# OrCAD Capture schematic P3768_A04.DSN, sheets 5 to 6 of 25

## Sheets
5 0020_M.2 KEY-E _WIFI_BT_: size Custom
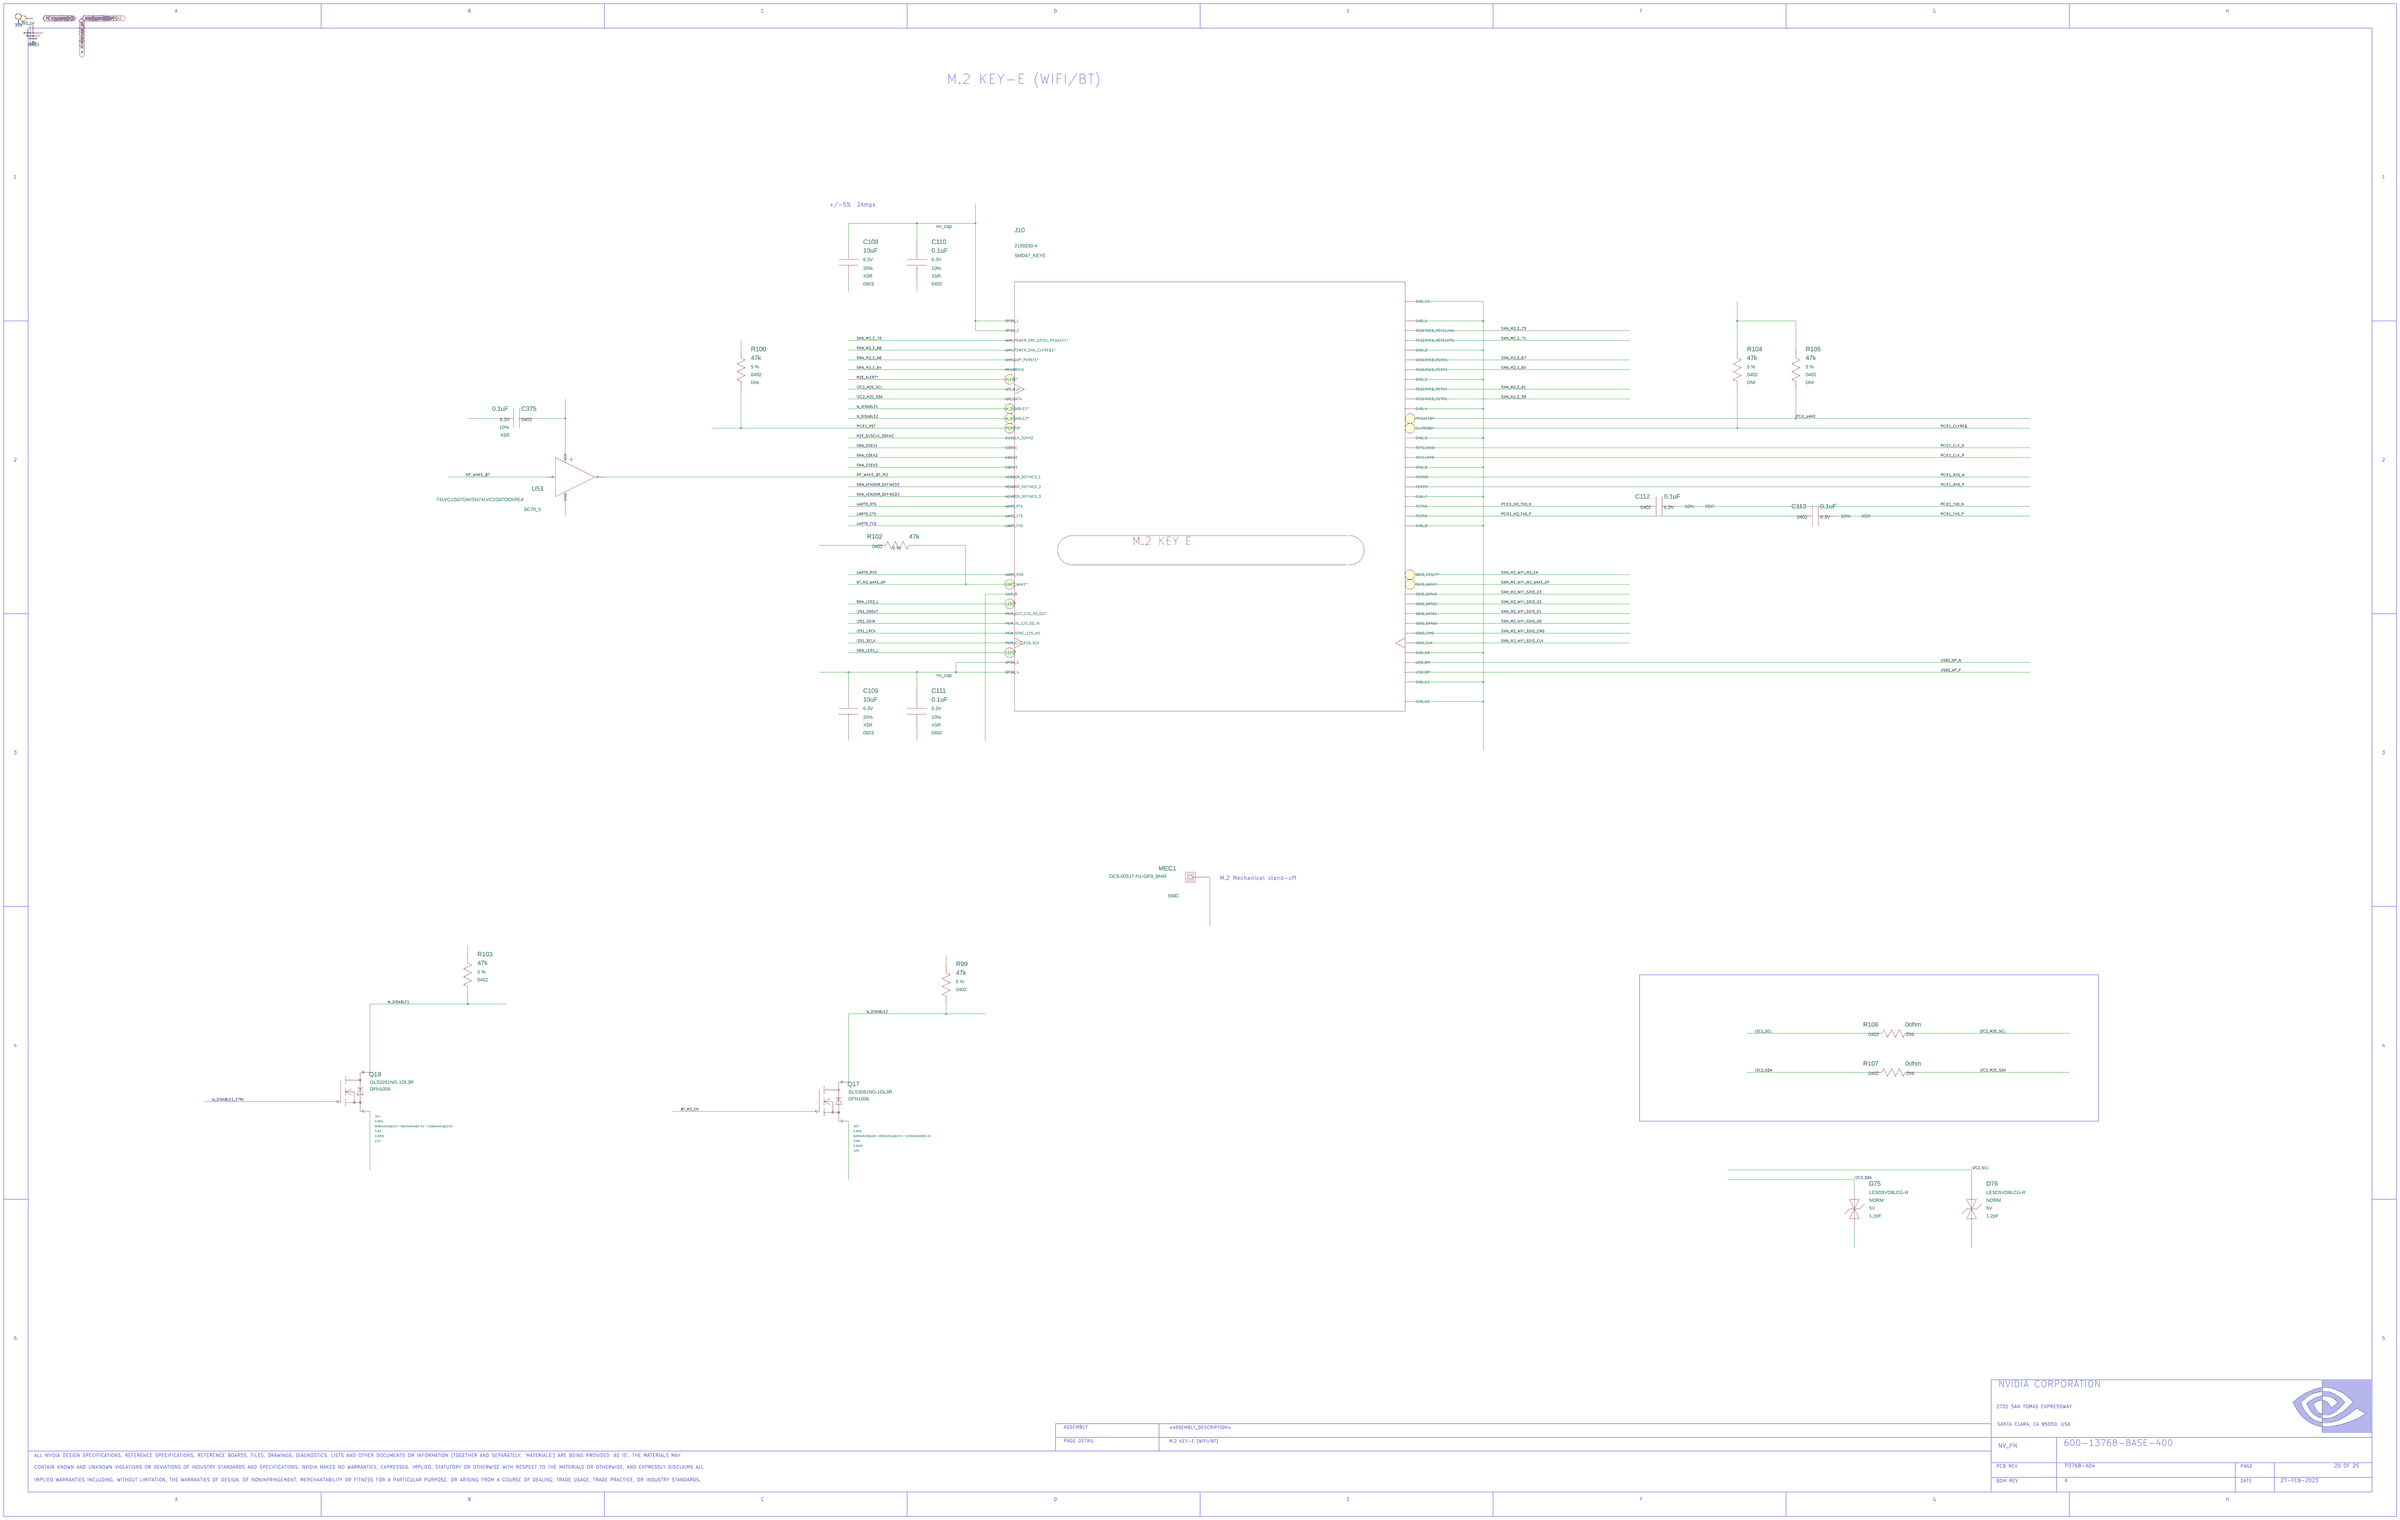
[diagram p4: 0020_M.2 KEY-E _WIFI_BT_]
6 0019_ETHERNET: size Custom
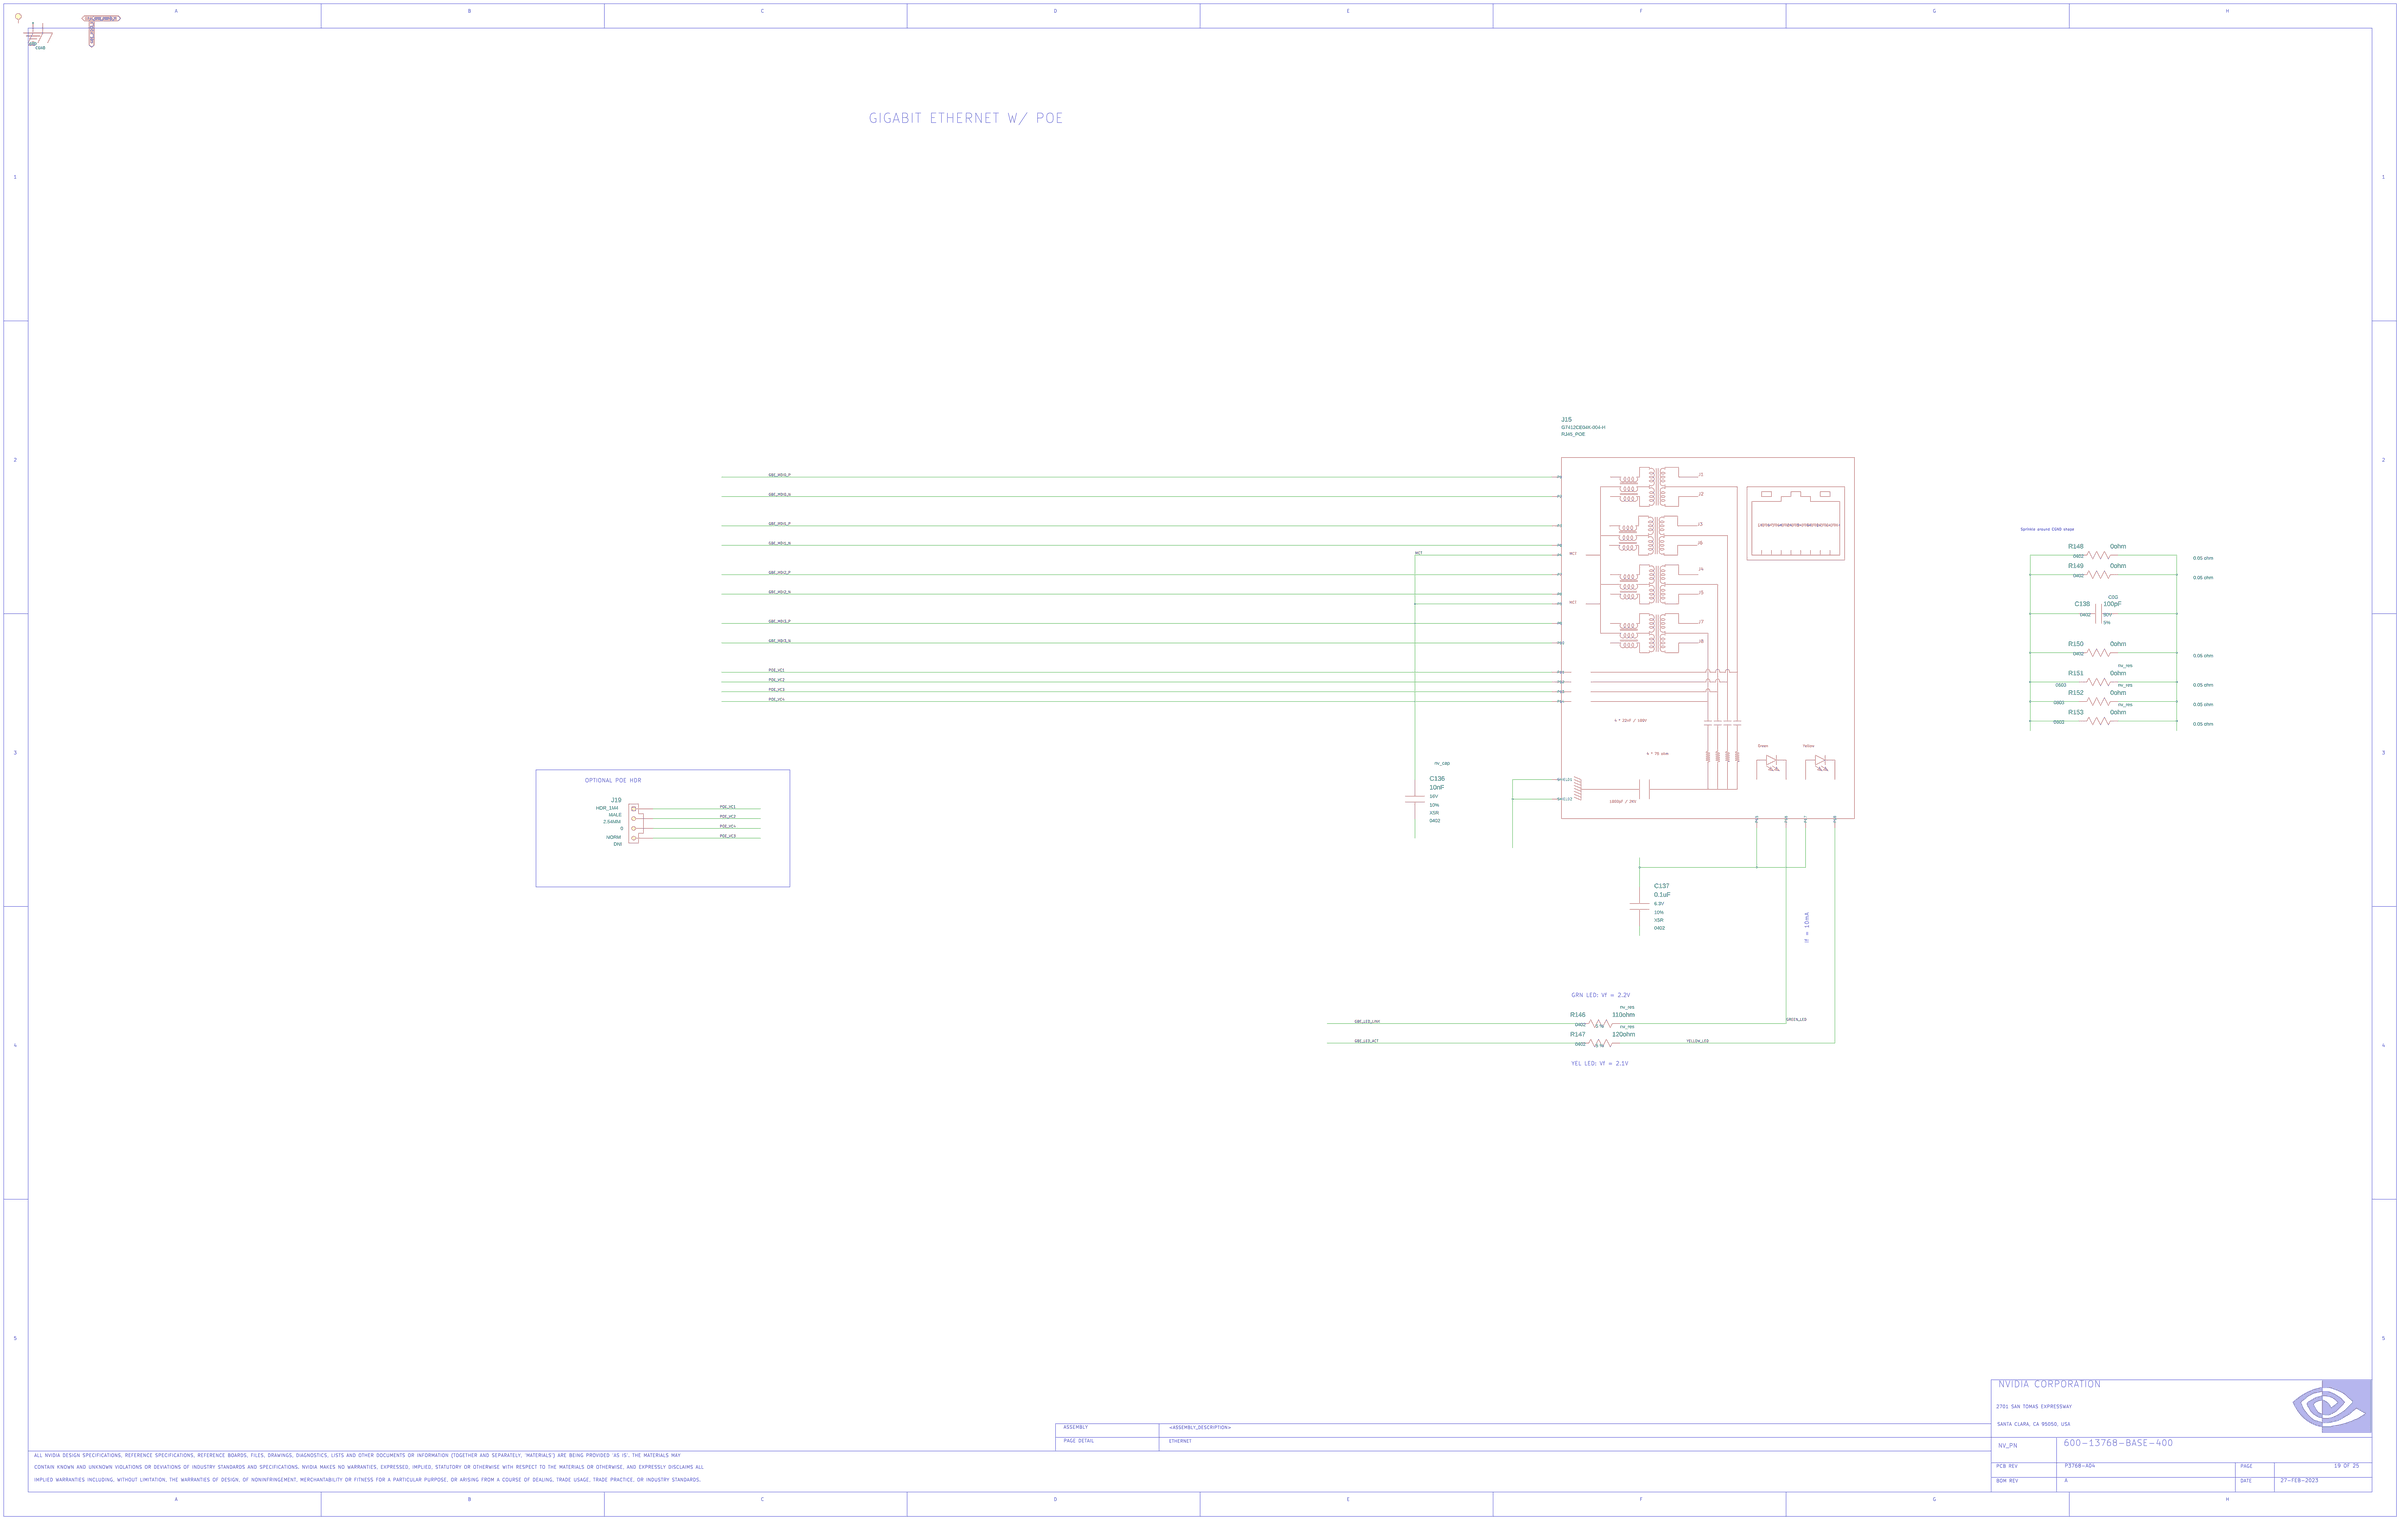
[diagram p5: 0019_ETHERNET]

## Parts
sheet 0019_ETHERNET
C136  10nF  [0402]
C137  0.1uF  [0402]
C138  100pF  [0402]
J15  CON_RJ45  [CON_RJ45_018_TH_RA_F_2LED]
J19  HDR_1X4  [CON_HDR_001X004_TH_ST_M_P025]
R146  110ohm  [0402]
R147  120ohm  [0402]
R148  0ohm  [0402]
R149  0ohm  [0402]
R150  0ohm  [0402]
R151  0ohm  [0603]
R152  0ohm  [0603]
R153  0ohm  [0603]
sheet 0020_M.2 KEY-E _WIFI_BT_
C108  10uF  [0603]
C109  10uF  [0603]
C110  0.1uF  [0402]
C111  0.1uF  [0402]
C112  0.1uF  [0402]
C113  0.1uF  [0402]
C375  0.1uF  [0402]
D75  D_ESD  [DIODE_SMD_010X006_B]
D76  D_ESD  [DIODE_SMD_010X006_B]
J10  CON_M2_PCI_EXP  [CON_MINIPEX_067_SMT_RA_M2_KEYE]
MEC1  MECH_SPECIAL  [MEC_STANDOFF_PTH_620C380P_M3_BNM]
Q17  Q_FET_N_ENH  [DFET_003_SMD_010X006_B]
Q18  Q_FET_N_ENH  [DFET_003_SMD_010X006_B]
R99  47k  [0402]
R100  47k  [0402]
R102  47k  [0402]
R103  47k  [0402]
R104  47k  [0402]
R105  47k  [0402]
R106  0ohm  [0402]
R107  0ohm  [0402]
U53  U_BUF_OD  [SC70_5]

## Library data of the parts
C136 = C#1: ASSEMBLY: ETHERNET; CDS_LIB: discrete; CDS_PART_NAME: C_0402-10NF,X5R,10%,16V,039-0024-000; CDS_PHYS_PART_NAME: C_0402-10NF,X5R,10%,16V,039-0024-000-039-0024-000,10NF; CDS_SEC: 1; CHIPS_PART_NAME: C; DEVICE_TYPENAME: C_0402-10NFX5R1016V039-0024-000-039-0024-00010NF; DRAWING: @P3768_A04_LIB.P3768_A04(SCH_1):PAGE19; MAT: X5R; MAX_VOLTAGE: 16V; NV_PN: 039-0024-000; PATH: I15; PHYS_PAGE: 19; PSPICETEMPLATE: X^@REFDES  %1    %2   @NV_PN; ROT: 0; SEC: 1; SIGNAL_MODEL: nv_cap; TOL: 10%; VER: 1; XY: (-4900,3550)
C137 = C#1: ASSEMBLY: ETHERNET; CDS_LIB: discrete; CDS_PART_NAME: C_0402-0.1UF,X5R,10%,6.3V,039-0007-000; CDS_PHYS_PART_NAME: C_0402-0.1UF,X5R,10%,6.3V,039-0007-000-0.1UF,039-0007-000; CDS_SEC: 1; CHIPS_PART_NAME: C; DEVICE_TYPENAME: C_0402-01UFX5R1063V039-0007-000-01UF039-0007-000; DRAWING: @P3768_A04_LIB.P3768_A04(SCH_1):PAGE19; ESL: N/A; ESR: N/A; MAT: X5R; MAX_VOLTAGE: 6.3V; NV_PN: 039-0007-000; PATH: I13; PHYS_PAGE: 19; PSPICETEMPLATE: X^@REFDES  %1    %2   @NV_PN; ROT: 0; SEC: 1; SIGNAL_MODEL: nv_cap; TOL: 10%; VER: 1; XY: (-3750,3000)
C138 = C: ASSEMBLY: ETHERNET; CDS_LIB: discrete; CDS_PART_NAME: C_0402-100PF,C0G,5%,50V,035-0012-000; CDS_PHYS_PART_NAME: C_0402-100PF,C0G,5%,50V,035-0012-000-035-0012-000,100PF; CDS_SEC: 1; DEVICE_TYPENAME: C_0402-100PFC0G550V035-0012-000-035-0012-000100PF; DRAWING: @P3768_A04_LIB.P3768_A04(SCH_1):PAGE19; ESL: N/A; ESR: N/A; MAT: C0G; MAX_VOLTAGE: 50V; NV_PN: 035-0012-000; PATH: I5; PHYS_PAGE: 19; PSPICETEMPLATE: X^@REFDES  %1    %2   @NV_PN; ROT: 0; SEC: 1; SIGNAL_MODEL: nv_cap; TOL: 5%; VER: 2; XY: (-1400,4500)
J15 = CON_RJ45: ANGLE: 90; ASSEMBLY: ETHERNET; CDS_LIB: electro_mechanic; CDS_PART_NAME: CON_RJ45_RJ45_POE-G7412CE04K-004-H,FEMALE,1.27MM,90,NO,YES,YES,YES,YES,54 V,600 MA,064-0404-000; CDS_PHYS_PART_NAME: CON_RJ45_RJ45_POE-G7412CE04K-004-H,FEMALE,1.27MM,90,NO,YES,YES,YES,YES,54 V,600 MA,064-0404-000-064-0404-000; CDS_SEC: 1; DEVICE_TYPENAME: CON_RJ45_RJ45_POE-G7412CE04K-004-HFEMALE127MM90NOYESYESYESYES54V600MA064-0404-000-064-0404-000; DRAWING: @P3768_A04_LIB.P3768_A04(SCH_1):PAGE19; EMI_GROUND_TAB: YES; GENDER: FEMALE; LATCHING: YES; MAX_CURRENT: 600 mA; MAX_VOLTAGE: 54 V; NV_NAME: G7412CE04K-004-H; NV_PN: 064-0404-000; PACK_TYPE: RJ45_POE; PATH: I1; PHYS_PAGE: 19; PITCH: 1.27mm; REFLOW: NO; ROT: 0; SEC: 1; SHIELDED: YES; SHROUDED: YES; VER: 15; XY: (-3400,4450)
J19 = HDR_1X4: ANGLE: 0; ASSEMBLY: ETHERNET; CDS_LIB: electro_mechanic; CDS_PART_NAME: HDR_1X4_NORM-HDR_1M4,MALE,2.54MM,0,NO,N/A,NO,500VAC,3A,074-0062-000; CDS_PHYS_PART_NAME: HDR_1X4_NORM-HDR_1M4,MALE,2.54MM,0,NO,N/A,NO,500VAC,3A,074-0062-000-074-0062-000; CDS_SEC: 1; DEVICE_TYPENAME: HDR_1X4_NORM-HDR_1M4MALE254MM0NONANO500VAC3A074-0062-000-074-0062-000; DRAWING: @P3768_A04_LIB.P3768_A04(SCH_1):PAGE19; GENDER: MALE; LATCHING: NO; MAX_CURRENT: 3A; MAX_VOLTAGE: 500VAC; NV_NAME: HDR_1M4; NV_PN: 074-0062-000; PACK_TYPE: NORM; PATH: I29; PHYS_PAGE: 19; PITCH: 2.54MM; REFLOW: NO; ROT: 2; SEC: 1; SHROUDED: N/A; SKU: DNI; VER: 1; XY: (-8900,3500)
R146 = R#1: ASSEMBLY: ETHERNET; CDS_LIB: discrete; CDS_PART_NAME: R_0402-110OHM,5 %,62.5MW,195-0492-000; CDS_PHYS_PART_NAME: R_0402-110OHM,5 %,62.5MW,195-0492-000-110OHM,195-0492-000; CDS_SEC: 1; CHIPS_PART_NAME: R; DEVICE_TYPENAME: R_0402-110OHM5625MW195-0492-000-110OHM195-0492-000; DRAWING: @P3768_A04_LIB.P3768_A04(SCH_1):PAGE19; MAX_WATTAGE: 62.5mW; NV_PN: 195-0492-000; PATH: I17; PHYS_PAGE: 19; PSPICETEMPLATE: X^@REFDES  %1    %2   @NV_PN; ROT: 0; SEC: 1; SIGNAL_MODEL: nv_res; TOL: 5 %; VER: 1; XY: (-3950,2400)
R147 = R#1: ASSEMBLY: ETHERNET; CDS_LIB: discrete; CDS_PART_NAME: R_0402-120OHM,5 %,62.5MW,195-0499-000; CDS_PHYS_PART_NAME: R_0402-120OHM,5 %,62.5MW,195-0499-000-120OHM,195-0499-000; CDS_SEC: 1; CHIPS_PART_NAME: R; DEVICE_TYPENAME: R_0402-120OHM5625MW195-0499-000-120OHM195-0499-000; DRAWING: @P3768_A04_LIB.P3768_A04(SCH_1):PAGE19; MAX_WATTAGE: 62.5mW; NV_PN: 195-0499-000; PATH: I18; PHYS_PAGE: 19; PSPICETEMPLATE: X^@REFDES  %1    %2   @NV_PN; ROT: 0; SEC: 1; SIGNAL_MODEL: nv_res; TOL: 5 %; VER: 1; XY: (-3950,2300)
R148 = R#1: ASSEMBLY: ETHERNET; CDS_LIB: discrete; CDS_PART_NAME: R_0402-0OHM,0.05 OHM,62.5MW,195-2655-000; CDS_PHYS_PART_NAME: R_0402-0OHM,0.05 OHM,62.5MW,195-2655-000-0OHM,195-2655-000; CDS_SEC: 1; CHIPS_PART_NAME: R; DEVICE_TYPENAME: R_0402-0OHM005OHM625MW195-2655-000-0OHM195-2655-000; DRAWING: @P3768_A04_LIB.P3768_A04(SCH_1):PAGE19; MAX_WATTAGE: 62.5mW; NV_PN: 195-2655-000; PATH: I2; PHYS_PAGE: 19; PSPICETEMPLATE: X^@REFDES  %1    %2   @NV_PN; ROT: 0; SEC: 1; SIGNAL_MODEL: nv_res; TOL: 0.05 ohm; VER: 1; XY: (-1400,4800)
R149 = R#1: ASSEMBLY: ETHERNET; CDS_LIB: discrete; CDS_PART_NAME: R_0402-0OHM,0.05 OHM,62.5MW,195-2655-000; CDS_PHYS_PART_NAME: R_0402-0OHM,0.05 OHM,62.5MW,195-2655-000-0OHM,195-2655-000; CDS_SEC: 1; CHIPS_PART_NAME: R; DEVICE_TYPENAME: R_0402-0OHM005OHM625MW195-2655-000-0OHM195-2655-000; DRAWING: @P3768_A04_LIB.P3768_A04(SCH_1):PAGE19; MAX_WATTAGE: 62.5mW; NV_PN: 195-2655-000; PATH: I4; PHYS_PAGE: 19; PSPICETEMPLATE: X^@REFDES  %1    %2   @NV_PN; ROT: 0; SEC: 1; SIGNAL_MODEL: nv_res; TOL: 0.05 ohm; VER: 1; XY: (-1400,4700)
R150 = R#1: ASSEMBLY: ETHERNET; CDS_LIB: discrete; CDS_PART_NAME: R_0402-0OHM,0.05 OHM,62.5MW,195-2655-000; CDS_PHYS_PART_NAME: R_0402-0OHM,0.05 OHM,62.5MW,195-2655-000-0OHM,195-2655-000; CDS_SEC: 1; CHIPS_PART_NAME: R; DEVICE_TYPENAME: R_0402-0OHM005OHM625MW195-2655-000-0OHM195-2655-000; DRAWING: @P3768_A04_LIB.P3768_A04(SCH_1):PAGE19; MAX_WATTAGE: 62.5mW; NV_PN: 195-2655-000; PATH: I6; PHYS_PAGE: 19; PSPICETEMPLATE: X^@REFDES  %1    %2   @NV_PN; ROT: 0; SEC: 1; SIGNAL_MODEL: nv_res; TOL: 0.05 ohm; VER: 1; XY: (-1400,4300)
R151 = R#1: ASSEMBLY: ETHERNET; CDS_LIB: discrete; CDS_PART_NAME: R_0603-0OHM,0.05 OHM,0MW,195-1765-000; CDS_PHYS_PART_NAME: R_0603-0OHM,0.05 OHM,0MW,195-1765-000-0OHM,195-1765-000; CDS_SEC: 1; CHIPS_PART_NAME: R; DEVICE_TYPENAME: R_0603-0OHM005OHM0MW195-1765-000-0OHM195-1765-000; DRAWING: @P3768_A04_LIB.P3768_A04(SCH_1):PAGE19; MAX_WATTAGE: 0mW; NV_PN: 195-1765-000; PATH: I7; PHYS_PAGE: 19; PSPICETEMPLATE: X^@REFDES  %1    %2   @NV_PN; ROT: 0; SEC: 1; SIGNAL_MODEL: nv_res; TOL: 0.05 ohm; VER: 1; XY: (-1400,4150)
R152 = R#1: ASSEMBLY: ETHERNET; CDS_LIB: discrete; CDS_PART_NAME: R_0603-0OHM,0.05 OHM,0MW,195-1765-000; CDS_PHYS_PART_NAME: R_0603-0OHM,0.05 OHM,0MW,195-1765-000-0OHM,195-1765-000; CDS_SEC: 1; CHIPS_PART_NAME: R; DEVICE_TYPENAME: R_0603-0OHM005OHM0MW195-1765-000-0OHM195-1765-000; DRAWING: @P3768_A04_LIB.P3768_A04(SCH_1):PAGE19; MAX_WATTAGE: 0mW; NV_PN: 195-1765-000; PATH: I8; PHYS_PAGE: 19; PSPICETEMPLATE: X^@REFDES  %1    %2   @NV_PN; ROT: 0; SEC: 1; SIGNAL_MODEL: nv_res; TOL: 0.05 ohm; VER: 1; XY: (-1400,4050)
R153 = R#1: ASSEMBLY: ETHERNET; CDS_LIB: discrete; CDS_PART_NAME: R_0603-0OHM,0.05 OHM,0MW,195-1765-000; CDS_PHYS_PART_NAME: R_0603-0OHM,0.05 OHM,0MW,195-1765-000-0OHM,195-1765-000; CDS_SEC: 1; CHIPS_PART_NAME: R; DEVICE_TYPENAME: R_0603-0OHM005OHM0MW195-1765-000-0OHM195-1765-000; DRAWING: @P3768_A04_LIB.P3768_A04(SCH_1):PAGE19; MAX_WATTAGE: 0mW; NV_PN: 195-1765-000; PATH: I9; PHYS_PAGE: 19; PSPICETEMPLATE: X^@REFDES  %1    %2   @NV_PN; ROT: 0; SEC: 1; SIGNAL_MODEL: nv_res; TOL: 0.05 ohm; VER: 1; XY: (-1400,3950)
C108 = C#1: ASSEMBLY: M2_WIFIBT; CDS_LIB: discrete; CDS_PART_NAME: C_0603-10UF,X5R,20%,6.3V,032-2136-000; CDS_PHYS_PART_NAME: C_0603-10UF,X5R,20%,6.3V,032-2136-000-032-2136-000,10UF; CDS_SEC: 1; CHIPS_PART_NAME: C; DEVICE_TYPENAME: C_0603-10UFX5R2063V032-2136-000-032-2136-00010UF; DRAWING: @P3768_A04_LIB.P3768_A04(SCH_1):PAGE20; MAT: X5R; MAX_VOLTAGE: 6.3V; NV_PN: 032-2136-000; PATH: I26; PHYS_PAGE: 20; PSPICETEMPLATE: X^@REFDES  %1    %2   @NV_PN; ROT: 0; SEC: 1; SIGNAL_MODEL: DEFAULT_CAPACITOR_1e+07pF_2_1; TOL: 20%; VER: 1; XY: (-7800,6300)
C109 = C#1: ASSEMBLY: M2_WIFIBT; CDS_LIB: discrete; CDS_PART_NAME: C_0603-10UF,X5R,20%,6.3V,032-2136-000; CDS_PHYS_PART_NAME: C_0603-10UF,X5R,20%,6.3V,032-2136-000-032-2136-000,10UF; CDS_SEC: 1; CHIPS_PART_NAME: C; DEVICE_TYPENAME: C_0603-10UFX5R2063V032-2136-000-032-2136-00010UF; DRAWING: @P3768_A04_LIB.P3768_A04(SCH_1):PAGE20; MAT: X5R; MAX_VOLTAGE: 6.3V; NV_PN: 032-2136-000; PATH: I36; PHYS_PAGE: 20; PSPICETEMPLATE: X^@REFDES  %1    %2   @NV_PN; ROT: 0; SEC: 1; SIGNAL_MODEL: DEFAULT_CAPACITOR_1e+07pF_2_1; TOL: 20%; VER: 1; XY: (-7800,4000)
C110 = C#1: ASSEMBLY: M2_WIFIBT; CDS_LIB: discrete; CDS_PART_NAME: C_0402-0.1UF,X5R,10%,6.3V,039-0007-000; CDS_PHYS_PART_NAME: C_0402-0.1UF,X5R,10%,6.3V,039-0007-000-0.1UF,039-0007-000; CDS_SEC: 1; CHIPS_PART_NAME: C; DEVICE_TYPENAME: C_0402-01UFX5R1063V039-0007-000-01UF039-0007-000; DRAWING: @P3768_A04_LIB.P3768_A04(SCH_1):PAGE20; MAT: X5R; MAX_VOLTAGE: 6.3V; NV_PN: 039-0007-000; PATH: I25; PHYS_PAGE: 20; PSPICETEMPLATE: X^@REFDES  %1    %2   @NV_PN; ROT: 0; SEC: 1; SIGNAL_MODEL: nv_cap; TOL: 10%; VER: 1; XY: (-7450,6300)
C111 = C#1: ASSEMBLY: M2_WIFIBT; CDS_LIB: discrete; CDS_PART_NAME: C_0402-0.1UF,X5R,10%,6.3V,039-0007-000; CDS_PHYS_PART_NAME: C_0402-0.1UF,X5R,10%,6.3V,039-0007-000-0.1UF,039-0007-000; CDS_SEC: 1; CHIPS_PART_NAME: C; DEVICE_TYPENAME: C_0402-01UFX5R1063V039-0007-000-01UF039-0007-000; DRAWING: @P3768_A04_LIB.P3768_A04(SCH_1):PAGE20; MAT: X5R; MAX_VOLTAGE: 6.3V; NV_PN: 039-0007-000; PATH: I34; PHYS_PAGE: 20; PSPICETEMPLATE: X^@REFDES  %1    %2   @NV_PN; ROT: 0; SEC: 1; SIGNAL_MODEL: nv_cap; TOL: 10%; VER: 1; XY: (-7450,4000)
C112 = C: ASSEMBLY: M2_WIFIBT; CDS_LIB: discrete; CDS_PART_NAME: C_0402-0.1UF,X5R,10%,6.3V,039-0007-000; CDS_PHYS_PART_NAME: C_0402-0.1UF,X5R,10%,6.3V,039-0007-000-0.1UF,039-0007-000; CDS_SEC: 1; DEVICE_TYPENAME: C_0402-01UFX5R1063V039-0007-000-01UF039-0007-000; DRAWING: @P3768_A04_LIB.P3768_A04(SCH_1):PAGE20; MAT: X5R; MAX_VOLTAGE: 6.3V; NV_PN: 039-0007-000; PATH: I16; PHYS_PAGE: 20; PSPICETEMPLATE: X^@REFDES  %1    %2   @NV_PN; ROT: 0; SEC: 1; SIGNAL_MODEL: nv_cap; TOL: 10%; VER: 2; XY: (-3650,5050)
C113 = C: ASSEMBLY: M2_WIFIBT; CDS_LIB: discrete; CDS_PART_NAME: C_0402-0.1UF,X5R,10%,6.3V,039-0007-000; CDS_PHYS_PART_NAME: C_0402-0.1UF,X5R,10%,6.3V,039-0007-000-0.1UF,039-0007-000; CDS_SEC: 1; DEVICE_TYPENAME: C_0402-01UFX5R1063V039-0007-000-01UF039-0007-000; DRAWING: @P3768_A04_LIB.P3768_A04(SCH_1):PAGE20; MAT: X5R; MAX_VOLTAGE: 6.3V; NV_PN: 039-0007-000; PATH: I17; PHYS_PAGE: 20; PSPICETEMPLATE: X^@REFDES  %1    %2   @NV_PN; ROT: 0; SEC: 1; SIGNAL_MODEL: nv_cap; TOL: 10%; VER: 2; XY: (-2850,5000)
C375 = C: ASSEMBLY: M2_WIFIBT; CDS_LIB: discrete; CDS_PART_NAME: C_0402-0.1UF,X5R,10%,6.3V,039-0007-000; CDS_PHYS_PART_NAME: C_0402-0.1UF,X5R,10%,6.3V,039-0007-000-0.1UF,039-0007-000; CDS_SEC: 1; DEVICE_TYPENAME: C_0402-01UFX5R1063V039-0007-000-01UF039-0007-000; DRAWING: @P3768_A04_LIB.P3768_A04(SCH_1):PAGE20; MAT: X5R; MAX_VOLTAGE: 6.3V; NV_PN: 039-0007-000; PATH: I143; PHYS_PAGE: 20; ROT: 2; SEC: 1; SIGNAL_MODEL: nv_cap; TOL: 10%; VER: 2; XY: (-9500,5500)
D75 = D_ESD: ASSEMBLY: M2_WIFIBT; BREAKDOWN_VOLTAGE_MIN_TYP: 5.5V; CAPACITANCE_MAX_TYP: 1.2pF; CDS_LIB: discrete; CDS_PART_NAME: D_ESD_NORM-LESD5VD8LCG-R,1 LINE,BI-DIRECTIONAL,5V,0.05UA,5.5V,10V@2A,1.2PF,090-0172-000; CDS_PHYS_PART_NAME: D_ESD_NORM-LESD5VD8LCG-R,1 LINE,BI-DIRECTIONAL,5V,0.05UA,5.5V,10V@2A,1.2PF,090-0172-000-090-0172-000; CDS_SEC: 1; CLAMPING_VOLTAGE: 10V@2A; CONFIGURATION: 1 Line; DEVICE_TYPENAME: D_ESD_NORM-LESD5VD8LCG-R1LINEBI-DIRECTIONAL5V005UA55V10V2A12PF090-0172-000-090-0172-000; DRAWING: @P3768_A04_LIB.P3768_A04(SCH_1):PAGE20; MAX_REVERSE_LEAKAGE_CURRENT: 0.05uA; MAX_REVERSE_VOLTAGE: 5V; NV_NAME: LESD5VD8LCG-R; NV_PN: 090-0172-000; PACK_TYPE: NORM; PATH: I40; PHYS_PAGE: 20; POLARITY: Bi-Directional; ROT: 0; SEC: 1; VER: 2; XY: (-2650,1450)
D76 = D_ESD: ASSEMBLY: M2_WIFIBT; BREAKDOWN_VOLTAGE_MIN_TYP: 5.5V; CAPACITANCE_MAX_TYP: 1.2pF; CDS_LIB: discrete; CDS_PART_NAME: D_ESD_NORM-LESD5VD8LCG-R,1 LINE,BI-DIRECTIONAL,5V,0.05UA,5.5V,10V@2A,1.2PF,090-0172-000; CDS_PHYS_PART_NAME: D_ESD_NORM-LESD5VD8LCG-R,1 LINE,BI-DIRECTIONAL,5V,0.05UA,5.5V,10V@2A,1.2PF,090-0172-000-090-0172-000; CDS_SEC: 1; CLAMPING_VOLTAGE: 10V@2A; CONFIGURATION: 1 Line; DEVICE_TYPENAME: D_ESD_NORM-LESD5VD8LCG-R1LINEBI-DIRECTIONAL5V005UA55V10V2A12PF090-0172-000-090-0172-000; DRAWING: @P3768_A04_LIB.P3768_A04(SCH_1):PAGE20; MAX_REVERSE_LEAKAGE_CURRENT: 0.05uA; MAX_REVERSE_VOLTAGE: 5V; NV_NAME: LESD5VD8LCG-R; NV_PN: 090-0172-000; PACK_TYPE: NORM; PATH: I38; PHYS_PAGE: 20; POLARITY: Bi-Directional; ROT: 0; SEC: 1; VER: 2; XY: (-2050,1450)
J10 = CON_M2_PCI_EXP: ANGLE: 90; ASSEMBLY: M2_WIFIBT; CDS_LIB: electro_mechanic; CDS_PART_NAME: CON_M2_PCI_EXP_SMD67_KEYE-2199230-4,FEMALE,0.5MM,90,N/A,NO,NO,NO,NO,50.0 V,0.5 A,080-1243-000; CDS_PHYS_PART_NAME: CON_M2_PCI_EXP_SMD67_KEYE-2199230-4,FEMALE,0.5MM,90,N/A,NO,NO,NO,NO,50.0 V,0.5 A,080-1243-000-080-1243-000; CDS_SEC: 1; DEVICE_TYPENAME: CON_M2_PCI_EXP_SMD67_KEYE-2199230-4FEMALE05MM90NANONONONO500V05A080-1243-000-080-1243-000; DRAWING: @P3768_A04_LIB.P3768_A04(SCH_1):PAGE20; EMI_GROUND_TAB: NO; GENDER: FEMALE; LATCHING: NO; MAX_CURRENT: 0.5 A; MAX_VOLTAGE: 50.0 V; NV_NAME: 2199230-4; NV_PN: 080-1243-000; PACK_TYPE: SMD67_KEYE; PATH: I155; PHYS_PAGE: 20; PITCH: 0.5mm; REFLOW: N/A; ROT: 0; SEC: 1; SHIELDED: NO; SHROUDED: NO; VER: 2; XY: (-5950,5100)
MEC1 = MECH_SPECIAL: ASSEMBLY: M2_WIFIBT; CDS_LIB: mechanic; CDS_PART_NAME: MECH_SPECIAL_SMD-DCS-00517-N1-GP3_BNM,155-0697-000; CDS_PHYS_PART_NAME: MECH_SPECIAL_SMD-DCS-00517-N1-GP3_BNM,155-0697-000-155-0697-000; CDS_SEC: 1; DEVICE_TYPENAME: MECH_SPECIAL_SMD-DCS-00517-N1-GP3_BNM155-0697-000-155-0697-000; DRAWING: @P3768_A04_LIB.P3768_A04(SCH_1):PAGE20; NV_NAME: DCS-00517-N1-GP3_BNM; NV_PN: 155-0697-000; PACK_TYPE: SMD; PATH: I158; PHYS_PAGE: 20; ROT: 2; SEC: 1; VER: 28; XY: (-6050,3150)
Q17 = Q_FET_N_ENH#1: ASSEMBLY: M2_WIFIBT; CDS_LIB: discrete; CDS_PART_NAME: Q_FET_N_ENH_DFN1006-GLS3261NG-1DL3R,30V,600MOHM@10V / 650MOHM@4.5V / 1200MOHM@2.5V,0.95A,3.8A,12V,0.83W,0NC@10V / 0NC@4.5V / 0NC@2.5V,300-1253-000; CDS_PHYS_PART_NAME: Q_FET_N_ENH_DFN1006-GLS3261NG-1DL3R,30V,600MOHM@10V / 650MOHM@4.5V / 1200MOHM@2.5V,0.95A,3.8A,12V,0.83W,0NC@10V / 0NC@4.5V / 0B; CDS_SEC: 1; CONTINUOUS_CURRENT: 0.95A; CaptureCellPackProp: Q_FET_N_ENH##1; DEVICE_TYPENAME: Q_FET_N_ENH_DFN1006-GLS3261NG-1DL3R30V600MOHM10V650MOHM45V1200MOHM25V095A38A12V083W0NC10V0NC45V0B; DRAWING: @P3768_A04_LIB.P3768_A04(SCH_1):PAGE20; MAX_CURRENT: 3.8A; MAX_VOLTAGE: 30V; MAX_WATTAGE: 0.83W; NV_NAME: GLS3261NG-1DL3R; NV_PN: 300-1253-000; PACK_TYPE: DFN1006; PATH: I73; PHYS_PAGE: 20; Q_G: 0nC@10V / 0nC@4.5V / 0nC@2.5V; ROT: 0; R_DS_ON: 600mohm@10V / 650mohm@4.5V / 1200mohm@2.5V; SEC: 1; VER: 2; V_BE_GS: 12V; XY: (-7900,2000)
Q18 = Q_FET_N_ENH#1: ASSEMBLY: M2_WIFIBT; CDS_LIB: discrete; CDS_PART_NAME: Q_FET_N_ENH_DFN1006-GLS3261NG-1DL3R,30V,600MOHM@10V / 650MOHM@4.5V / 1200MOHM@2.5V,0.95A,3.8A,12V,0.83W,0NC@10V / 0NC@4.5V / 0NC@2.5V,300-1253-000; CDS_PHYS_PART_NAME: Q_FET_N_ENH_DFN1006-GLS3261NG-1DL3R,30V,600MOHM@10V / 650MOHM@4.5V / 1200MOHM@2.5V,0.95A,3.8A,12V,0.83W,0NC@10V / 0NC@4.5V / 0B; CDS_SEC: 1; CONTINUOUS_CURRENT: 0.95A; CaptureCellPackProp: Q_FET_N_ENH##1; DEVICE_TYPENAME: Q_FET_N_ENH_DFN1006-GLS3261NG-1DL3R30V600MOHM10V650MOHM45V1200MOHM25V095A38A12V083W0NC10V0NC45V0B; DRAWING: @P3768_A04_LIB.P3768_A04(SCH_1):PAGE20; MAX_CURRENT: 3.8A; MAX_VOLTAGE: 30V; MAX_WATTAGE: 0.83W; NV_NAME: GLS3261NG-1DL3R; NV_PN: 300-1253-000; PACK_TYPE: DFN1006; PATH: I44; PHYS_PAGE: 20; Q_G: 0nC@10V / 0nC@4.5V / 0nC@2.5V; ROT: 0; R_DS_ON: 600mohm@10V / 650mohm@4.5V / 1200mohm@2.5V; SEC: 1; VER: 2; V_BE_GS: 12V; XY: (-10350,2050)
R99 = R: ASSEMBLY: M2_WIFIBT; CDS_LIB: discrete; CDS_PART_NAME: R_0402-47K,5 %,62.5MW,195-0599-000; CDS_PHYS_PART_NAME: R_0402-47K,5 %,62.5MW,195-0599-000-195-0599-000,47K; CDS_SEC: 1; DEVICE_TYPENAME: R_0402-47K5625MW195-0599-000-195-0599-00047K; DRAWING: @P3768_A04_LIB.P3768_A04(SCH_1):PAGE20; MAX_WATTAGE: 62.5mW; NV_PN: 195-0599-000; PATH: I72; PHYS_PAGE: 20; PSPICETEMPLATE: X^@REFDES  %1    %2   @NV_PN; ROT: 0; SEC: 1; SIGNAL_MODEL: nv_res; TOL: 5 %; VER: 2; XY: (-7300,2600)
R100 = R: ASSEMBLY: M2_WIFIBT; CDS_LIB: discrete; CDS_PART_NAME: R_0402-47K,5 %,62.5MW,195-0599-000; CDS_PHYS_PART_NAME: R_0402-47K,5 %,62.5MW,195-0599-000-195-0599-000,47K; CDS_SEC: 1; DEVICE_TYPENAME: R_0402-47K5625MW195-0599-000-195-0599-00047K; DRAWING: @P3768_A04_LIB.P3768_A04(SCH_1):PAGE20; MAX_WATTAGE: 62.5mW; NV_PN: 195-0599-000; PATH: I52; PHYS_PAGE: 20; PSPICETEMPLATE: X^@REFDES  %1    %2   @NV_PN; ROT: 0; SEC: 1; SIGNAL_MODEL: nv_res; SKU: DNI; TOL: 5 %; VER: 2; XY: (-8350,5750)
R102 = R#1: ASSEMBLY: M2_WIFIBT; CDS_LIB: discrete; CDS_PART_NAME: R_0402-47K,5 %,62.5MW,195-0599-000; CDS_PHYS_PART_NAME: R_0402-47K,5 %,62.5MW,195-0599-000-195-0599-000,47K; CDS_SEC: 1; CHIPS_PART_NAME: R; DEVICE_TYPENAME: R_0402-47K5625MW195-0599-000-195-0599-00047K; DRAWING: @P3768_A04_LIB.P3768_A04(SCH_1):PAGE20; MAX_WATTAGE: 62.5mW; NV_PN: 195-0599-000; PATH: I30; PHYS_PAGE: 20; PSPICETEMPLATE: X^@REFDES  %1    %2   @NV_PN; ROT: 0; SEC: 1; SIGNAL_MODEL: nv_res; TOL: 5 %; VER: 1; XY: (-7550,4850)
R103 = R: ASSEMBLY: M2_WIFIBT; CDS_LIB: discrete; CDS_PART_NAME: R_0402-47K,5 %,62.5MW,195-0599-000; CDS_PHYS_PART_NAME: R_0402-47K,5 %,62.5MW,195-0599-000-195-0599-000,47K; CDS_SEC: 1; DEVICE_TYPENAME: R_0402-47K5625MW195-0599-000-195-0599-00047K; DRAWING: @P3768_A04_LIB.P3768_A04(SCH_1):PAGE20; MAX_WATTAGE: 62.5mW; NV_PN: 195-0599-000; PATH: I43; PHYS_PAGE: 20; PSPICETEMPLATE: X^@REFDES  %1    %2   @NV_PN; ROT: 0; SEC: 1; SIGNAL_MODEL: nv_res; TOL: 5 %; VER: 2; XY: (-9750,2650)
R104 = R: ASSEMBLY: M2_WIFIBT; CDS_LIB: discrete; CDS_PART_NAME: R_0402-47K,5 %,62.5MW,195-0599-000; CDS_PHYS_PART_NAME: R_0402-47K,5 %,62.5MW,195-0599-000-195-0599-000,47K; CDS_SEC: 1; DEVICE_TYPENAME: R_0402-47K5625MW195-0599-000-195-0599-00047K; DRAWING: @P3768_A04_LIB.P3768_A04(SCH_1):PAGE20; MAX_WATTAGE: 62.5mW; NV_PN: 195-0599-000; PATH: I15; PHYS_PAGE: 20; PSPICETEMPLATE: X^@REFDES  %1    %2   @NV_PN; ROT: 0; SEC: 1; SIGNAL_MODEL: nv_res; SKU: DNI; TOL: 5 %; VER: 2; XY: (-3250,5750)
R105 = R: ASSEMBLY: M2_WIFIBT; CDS_LIB: discrete; CDS_PART_NAME: R_0402-47K,5 %,62.5MW,195-0599-000; CDS_PHYS_PART_NAME: R_0402-47K,5 %,62.5MW,195-0599-000-195-0599-000,47K; CDS_SEC: 1; DEVICE_TYPENAME: R_0402-47K5625MW195-0599-000-195-0599-00047K; DRAWING: @P3768_A04_LIB.P3768_A04(SCH_1):PAGE20; MAX_WATTAGE: 62.5mW; NV_PN: 195-0599-000; PATH: I14; PHYS_PAGE: 20; PSPICETEMPLATE: X^@REFDES  %1    %2   @NV_PN; ROT: 0; SEC: 1; SIGNAL_MODEL: nv_res; SKU: DNI; TOL: 5 %; VER: 2; XY: (-2950,5750)
R106 = R#1: ASSEMBLY: M2_WIFIBT; CDS_LIB: discrete; CDS_PART_NAME: R_0402-0OHM,0.05 OHM,62.5MW,195-2655-000; CDS_PHYS_PART_NAME: R_0402-0OHM,0.05 OHM,62.5MW,195-2655-000-0OHM,195-2655-000; CDS_SEC: 1; CHIPS_PART_NAME: R; DEVICE_TYPENAME: R_0402-0OHM005OHM625MW195-2655-000-0OHM195-2655-000; DRAWING: @P3768_A04_LIB.P3768_A04(SCH_1):PAGE20; MAX_WATTAGE: 62.5mW; NV_PN: 195-2655-000; PATH: I151; PHYS_PAGE: 20; PSPICETEMPLATE: X^@REFDES  %1    %2   @NV_PN; ROT: 0; SEC: 1; SIGNAL_MODEL: nv_res; SKU: DNI; TOL: 0.05 ohm; VER: 1; XY: (-2450,2350)
R107 = R#1: ASSEMBLY: M2_WIFIBT; CDS_LIB: discrete; CDS_PART_NAME: R_0402-0OHM,0.05 OHM,62.5MW,195-2655-000; CDS_PHYS_PART_NAME: R_0402-0OHM,0.05 OHM,62.5MW,195-2655-000-0OHM,195-2655-000; CDS_SEC: 1; CHIPS_PART_NAME: R; DEVICE_TYPENAME: R_0402-0OHM005OHM625MW195-2655-000-0OHM195-2655-000; DRAWING: @P3768_A04_LIB.P3768_A04(SCH_1):PAGE20; MAX_WATTAGE: 62.5mW; NV_PN: 195-2655-000; PATH: I152; PHYS_PAGE: 20; PSPICETEMPLATE: X^@REFDES  %1    %2   @NV_PN; ROT: 0; SEC: 1; SIGNAL_MODEL: nv_res; SKU: DNI; TOL: 0.05 ohm; VER: 1; XY: (-2450,2150)
U53 = U_BUF_OD: ASSEMBLY: M2_WIFIBT; CDS_LIB: logic; CDS_PART_NAME: U_BUF_OD_SC70_5-74LVC1G07GW/SN74LVC1G07DCKRE4,BUFFER - OPEN DRAIN,115-0138-000; CDS_PHYS_PART_NAME: U_BUF_OD_SC70_5-74LVC1G07GW/SN74LVC1G07DCKRE4,BUFFER - OPEN DRAIN,115-0138-000-115-0138-000; CDS_SEC: 1; DEVICE_TYPENAME: U_BUF_OD_SC70_5-74LVC1G07GWSN74LVC1G07DCKRE4BUFFER-OPENDRAIN115-0138-000-115-0138-000; DRAWING: @P3768_A04_LIB.P3768_A04(SCH_1):PAGE20; FUNCTION: Buffer - Open Drain; NV_NAME: 74LVC1G07GW/SN74LVC1G07DCKRE4; NV_PN: 115-0138-000; PATH: I156; PHYS_PAGE: 20; ROT: 0; SEC: 1; VER: 1; XY: (-9200,5200)

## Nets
GND: C108.2 C109.2 C110.2 C111.2 C136.2 C137.2 C138.1 C375.2 D75.2 D76.2 J10.1(GND_11) J10.7(GND_10) J10.18(GND_9) J10.33(GND_8) J10.39(GND_7) J10.45(GND_6) J10.51(GND_5) J10.57(GND_4) J10.63(GND_3) J10.69(GND_2) J10.75(GND_1) J10.76(GND_13) J10.77(GND_12) MEC1.1 Q17.2(S) Q18.2(S) R148.1 R149.1 R150.1 R151.1 R152.1 R153.1 U53.3(GND) ; also on sheet 1 2 3 4 7 8 9 10 11 12 13 14 15 16 17 18 19 21 25
VDD_1V8: C375.1 U53.5(VCC) ; also on sheet 1 2 3 8 12 14 19 21
VDD_3V3_SYS: C108.1 C109.1 C110.1 C111.1 C137.1 J10.2(3P3V_4) J10.4(3P3V_3) J10.72(3P3V_2) J10.74(3P3V_1) J15.15(P15) J15.17(P17) R99.1 R100.1 R102.1 R103.1 R104.1 R105.1 ; also on sheet 1 2 3 4 7 8 11 12 14 15 19 20 21
AP_WAKE_BT: U53.2(A) ; also on sheet 3
AP_WAKE_BT_M2: J10.42(VENDOR_DEFINED_1) U53.4(Y)
BT_M2_EN: Q17.1(G) ; also on sheet 20
BT_M2_WAKE_AP: J10.20(UART_WAKE*) R102.2 ; also on sheet 20
CGND: C138.2 J15.19(SHIELD1) J15.20(SHIELD2) R148.2 R149.2 R150.2 R151.2 R152.2 R153.2
GBE_LED_ACT: R147.1 ; also on sheet 20
GBE_LED_LINK: R146.1 ; also on sheet 20
GBE_MDI0_N: J15.2(P2) ; also on sheet 20
GBE_MDI0_P: J15.1(P1) ; also on sheet 20
GBE_MDI1_N: J15.6(P6) ; also on sheet 20
GBE_MDI1_P: J15.3(P3) ; also on sheet 20
GBE_MDI2_N: J15.8(P8) ; also on sheet 20
GBE_MDI2_P: J15.7(P7) ; also on sheet 20
GBE_MDI3_N: J15.10(P10) ; also on sheet 20
GBE_MDI3_P: J15.9(P9) ; also on sheet 20
GREEN_LED: J15.16(P16) R146.2
I2C2_M2E_SCL: J10.60(I2C_CLK) R106.2
I2C2_M2E_SDA: J10.58(I2C_DATA) R107.2
I2C2_SCL: D76.1 R106.1 ; also on sheet 1 3 4 21
I2C2_SDA: D75.1 R107.1 ; also on sheet 1 3 4 21
I2S1_LRCK: J10.10(PCM_SYNC_125_WS) ; also on sheet 20
I2S1_SCLK: J10.8(PCM_CLK_12S_SCK) ; also on sheet 20
I2S1_SDIN: J10.12(PCM_IN_12S_SD_IN) ; also on sheet 20
I2S1_SDOUT: J10.14(PCM_OUT_12S_SD_OUT) ; also on sheet 20
M2E_ALERT*: J10.62(ALERT*) ; also on sheet 3
M2E_SUSCLK_32KHZ: J10.50(SUSCLK_32KHZ) ; also on sheet 19
MCT: C136.1 J15.4(P4) J15.5(P5)
PCIE1_CLK_N: J10.49(REFCLKNO) ; also on sheet 19
PCIE1_CLK_P: J10.47(REFCLKPO) ; also on sheet 19
PCIE1_CLKREQ: J10.53(CLKREQO*) R104.2 ; also on sheet 19
PCIE1_M2_TX0_N: C112.1 J10.37(PETNO)
PCIE1_M2_TX0_P: C113.1 J10.35(PETPO)
PCIE1_RST: J10.52(PERST0*) R100.2 ; also on sheet 19
PCIE1_RX0_N: J10.43(PERNO) ; also on sheet 19
PCIE1_RX0_P: J10.41(PERPO) ; also on sheet 19
PCIE1_TX0_N: C112.2 ; also on sheet 19
PCIE1_TX0_P: C113.2 ; also on sheet 19
PCIE_WAKE: J10.55(PEWAKEO*) R105.2 ; also on sheet 3 4 19
POE_VC1: J15.11(P11) J19.1
POE_VC2: J15.12(P12) J19.2
POE_VC3: J15.13(P13) J19.4
POE_VC4: J15.14(P14) J19.3
SNN_COEX1: J10.48(COEX1)
SNN_COEX2: J10.46(COEX2)
SNN_COEX3: J10.44(COEX3)
SNN_LED1_L: J10.6(LED1*)
SNN_LED2_L: J10.16(LED2*)
SNN_M2_E_59: J10.59(RESERVED_PETP1)
SNN_M2_E_61: J10.61(RESERVED_PETN1)
SNN_M2_E_64: J10.64(RESERVED)
SNN_M2_E_65: J10.65(RESERVED_PERP1)
SNN_M2_E_66: J10.66(UIM_SWP_PERST1*)
SNN_M2_E_67: J10.67(RESERVED_PERN1)
SNN_M2_E_68: J10.68(UIM_POWER_SNK_CLKREQ1*)
SNN_M2_E_70: J10.70(UIM_POWER_SRC_GPIO1_PEWAKE1*)
SNN_M2_E_71: J10.71(RESERVED_REFCLKP1)
SNN_M2_E_73: J10.73(RESERVED_REFCLKN1)
SNN_M2_WIFI_M2_EN: J10.23(SDIO_RESET*)
SNN_M2_WIFI_M2_WAKE_AP: J10.21(SDIO_WAKE*)
SNN_M2_WIFI_SDIO_CLK: J10.9(SDIO_CLK)
SNN_M2_WIFI_SDIO_CMD: J10.11(SDIO_CMD)
SNN_M2_WIFI_SDIO_D0: J10.13(SDIO_DATAO)
SNN_M2_WIFI_SDIO_D1: J10.15(SDIO_DATA1)
SNN_M2_WIFI_SDIO_D2: J10.17(SDIO_DATA2)
SNN_M2_WIFI_SDIO_D3: J10.19(SDIO_DATA3)
SNN_VENDOR_DEFINED2: J10.40(VENDOR_DEFINED_2)
SNN_VENDOR_DEFINED3: J10.38(VENDOR_DEFINED_3)
UART0_CTS: J10.34(UART_CTS) ; also on sheet 21
UART0_RTS: J10.36(UART_RTS) ; also on sheet 21
UART0_RXD: J10.22(UART_RXD) ; also on sheet 21
UART0_TXD: J10.32(UART_TXD) ; also on sheet 21
USB2_AP_N: J10.5(USB_DM) ; also on sheet 20
USB2_AP_P: J10.3(USB_DP) ; also on sheet 20
W_DISABLE1: J10.56(W_DISABLE1*) Q18.3(D) R103.2
W_DISABLE1_CTRL: Q18.1(G) ; also on sheet 20
W_DISABLE2: J10.54(W_DISABLE2*) Q17.3(D) R99.2
YELLOW_LED: J15.18(P18) R147.2

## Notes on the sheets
sheet 5
- A
- B
- C
- D
- E
- F
- G
- H
- M.2 KEY-E (WIFI/BT)
- 1
- 1
- +/-5%  2Amps
- 2
- 2
- 3
- 3
- M.2 Mechanical stand-off
- 4
- 4
- 5
- 5
- NVIDIA CORPORATION
- 2701 SAN TOMAS EXPRESSWAY
- SANTA CLARA, CA 95050, USA
- ASSEMBLY
- <ASSEMBLY_DESCRIPTION>
- PAGE DETAIL
- M.2 KEY-E (WIFI/BT)
- 600-13768-BASE-400
- NV_PN
- ALL NVIDIA DESIGN SPECIFICATIONS, REFERENCE SPECIFICATIONS, REFERENCE BOARDS, FILES, DRAWINGS, DIAGNOSTICS, LISTS AND OTHER DOCUMENTS OR INFORMATION (TOGETHER AND SEPARATELY, 'MATERIALS') ARE BEING PROVIDED 'AS IS'. THE MATERIALS MAY
- P3768-A04
- 20 OF 25
- CONTAIN KNOWN AND UNKNOWN VIOLATIONS OR DEVIATIONS OF INDUSTRY STANDARDS AND SPECIFICATIONS. NVIDIA MAKES NO WARRANTIES, EXPRESSED, IMPLIED, STATUTORY OR OTHERWISE WITH RESPECT TO THE MATERIALS OR OTHERWISE, AND EXPRESSLY DISCLAIMS ALL
- PCB REV
- PAGE
- IMPLIED WARRANTIES INCLUDING, WITHOUT LIMITATION, THE WARRANTIES OF DESIGN, OF NONINFRINGEMENT, MERCHANTABILITY OR FITNESS FOR A PARTICULAR PURPOSE, OR ARISING FROM A COURSE OF DEALING, TRADE USAGE, TRADE PRACTICE, OR INDUSTRY STANDARDS.
- BOM REV
- A
- DATE
- 27-FEB-2023
- A
- B
- C
- D
- E
- F
- G
- H
sheet 6
- A
- B
- C
- D
- E
- F
- G
- H
- GIGABIT ETHERNET W/ POE
- 1
- 1
- 2
- 2
- Sprinkle around CGND shape
- 3
- 3
- OPTIONAL POE HDR
- If = 10mA
- GRN LED: Vf = 2.2V
- 4
- 4
- YEL LED: Vf = 2.1V
- 5
- 5
- NVIDIA CORPORATION
- 2701 SAN TOMAS EXPRESSWAY
- SANTA CLARA, CA 95050, USA
- ASSEMBLY
- <ASSEMBLY_DESCRIPTION>
- PAGE DETAIL
- ETHERNET
- 600-13768-BASE-400
- NV_PN
- ALL NVIDIA DESIGN SPECIFICATIONS, REFERENCE SPECIFICATIONS, REFERENCE BOARDS, FILES, DRAWINGS, DIAGNOSTICS, LISTS AND OTHER DOCUMENTS OR INFORMATION (TOGETHER AND SEPARATELY, 'MATERIALS') ARE BEING PROVIDED 'AS IS'. THE MATERIALS MAY
- P3768-A04
- 19 OF 25
- CONTAIN KNOWN AND UNKNOWN VIOLATIONS OR DEVIATIONS OF INDUSTRY STANDARDS AND SPECIFICATIONS. NVIDIA MAKES NO WARRANTIES, EXPRESSED, IMPLIED, STATUTORY OR OTHERWISE WITH RESPECT TO THE MATERIALS OR OTHERWISE, AND EXPRESSLY DISCLAIMS ALL
- PCB REV
- PAGE
- IMPLIED WARRANTIES INCLUDING, WITHOUT LIMITATION, THE WARRANTIES OF DESIGN, OF NONINFRINGEMENT, MERCHANTABILITY OR FITNESS FOR A PARTICULAR PURPOSE, OR ARISING FROM A COURSE OF DEALING, TRADE USAGE, TRADE PRACTICE, OR INDUSTRY STANDARDS.
- BOM REV
- A
- DATE
- 27-FEB-2023
- A
- B
- C
- D
- E
- F
- G
- H
